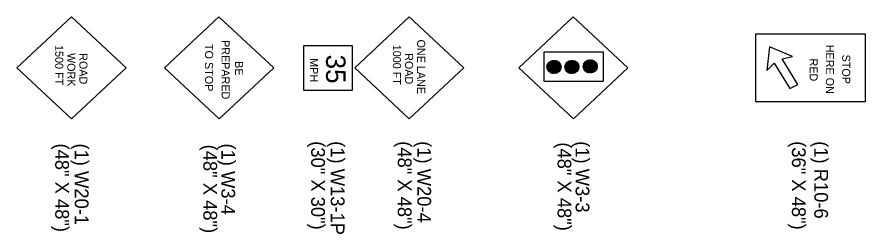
# Model space of a CAD drawing. Extents: x 1807779 to 1818251, y 673292 to 678849.
# Drawn here: x 1811173.9 to 1811561, y 676956.4 to 677055.5 of the extents above; entities that cross this region are included whole.
import ezdxf

# ---------------------------------------------------------------- set-up
doc = ezdxf.new("R2010")
doc.units = 0
doc.layers.add('Default', color=7, linetype='Continuous')

msp = doc.modelspace()

# ---------------------------------------------------------------- linework, layer by layer
at = {"layer": 'Default'}
for p, q in [((1811173.86, 677032.28), (1811198.79, 677055.53)), ((1811223.74, 677032.28), (1811198.79, 677055.53)), ((1811241.19, 677032.24), (1811266.09, 677055.53)), ((1811291.07, 677032.32), (1811266.09, 677055.53)), ((1811328.06, 677032.28), (1811352.98, 677055.53)), ((1811377.93, 677032.28), (1811352.98, 677055.53)), ((1811402.91, 677032.24), (1811427.81, 677055.53)), ((1811452.78, 677032.32), (1811427.81, 677055.53)), ((1811417.45, 677035.31), (1811421.84, 677031.21)), ((1811417.58, 677035.37), (1811421.91, 677031.33)), ((1811417.71, 677035.43), (1811421.97, 677031.46)), ((1811417.85, 677035.49), (1811422.03, 677031.59)), ((1811417.99, 677035.54), (1811422.09, 677031.72)), ((1811418.14, 677035.58), (1811422.13, 677031.86)), ((1811418.3, 677035.62), (1811422.18, 677032.01)), ((1811418.46, 677035.65), (1811422.21, 677032.16)), ((1811418.63, 677035.68), (1811422.24, 677032.32)), ((1811418.81, 677035.69), (1811422.26, 677032.49)), ((1811419, 677035.7), (1811422.26, 677032.66)), ((1811419.2, 677035.7), (1811422.26, 677032.85)), ((1811419.42, 677035.68), (1811422.24, 677033.05)), ((1811419.66, 677035.65), (1811422.21, 677033.27)), ((1811419.91, 677035.59), (1811422.14, 677033.51)), ((1811420.21, 677035.5), (1811422.04, 677033.79)), ((1811420.58, 677035.34), (1811421.87, 677034.13)), ((1811425.52, 677035.27), (1811429.94, 677031.15)), ((1811425.65, 677035.34), (1811430.01, 677031.27)), ((1811425.78, 677035.4), (1811430.08, 677031.39)), ((1811425.91, 677035.46), (1811430.14, 677031.51)), ((1811426.05, 677035.51), (1811430.2, 677031.65)), ((1811426.2, 677035.56), (1811430.25, 677031.78)), ((1811426.35, 677035.6), (1811430.3, 677031.92)), ((1811426.51, 677035.63), (1811430.33, 677032.07)), ((1811426.68, 677035.66), (1811430.37, 677032.23)), ((1811426.85, 677035.69), (1811430.39, 677032.39)), ((1811427.04, 677035.7), (1811430.4, 677032.56)), ((1811427.23, 677035.7), (1811430.41, 677032.74)), ((1811427.44, 677035.69), (1811430.4, 677032.94)), ((1811427.66, 677035.67), (1811430.37, 677033.15)), ((1811427.91, 677035.62), (1811430.32, 677033.37)), ((1811428.18, 677035.55), (1811430.25, 677033.63)), ((1811428.5, 677035.44), (1811430.12, 677033.93)), ((1811433.55, 677035.31), (1811438.08, 677031.1)), ((1811433.67, 677035.4), (1811438.17, 677031.2)), ((1811433.78, 677035.47), (1811438.25, 677031.31)), ((1811433.9, 677035.54), (1811438.32, 677031.42)), ((1811434.03, 677035.61), (1811438.4, 677031.54)), ((1811434.16, 677035.67), (1811438.46, 677031.66)), ((1811434.29, 677035.73), (1811438.53, 677031.79)), ((1811434.44, 677035.78), (1811438.58, 677031.92)), ((1811434.58, 677035.83), (1811438.63, 677032.06)), ((1811434.74, 677035.87), (1811438.68, 677032.2)), ((1811434.89, 677035.91), (1811438.72, 677032.35)), ((1811435.06, 677035.94), (1811438.75, 677032.5)), ((1811435.24, 677035.96), (1811438.77, 677032.67)), ((1811435.42, 677035.97), (1811438.79, 677032.84)), ((1811435.62, 677035.98), (1811438.79, 677033.02)), ((1811435.82, 677035.97), (1811438.78, 677033.21)), ((1811436.05, 677035.94), (1811438.75, 677033.42)), ((1811436.29, 677035.9), (1811438.71, 677033.65)), ((1811436.57, 677035.83), (1811438.63, 677033.9)), ((1811436.89, 677035.71), (1811438.51, 677034.2)), ((1811437.32, 677035.49), (1811438.27, 677034.61)), ((1811198.79, 677009.03), (1811173.86, 677032.28)), ((1811198.79, 677009.03), (1811223.74, 677032.28)), ((1811266.18, 677009.03), (1811241.19, 677032.24)), ((1811266.18, 677009.03), (1811291.07, 677032.32)), ((1811352.98, 677009.03), (1811328.06, 677032.28)), ((1811352.98, 677009.03), (1811377.93, 677032.28)), ((1811427.9, 677009.03), (1811402.91, 677032.24)), ((1811415.83, 677032.93), (1811419.29, 677029.71)), ((1811415.83, 677032.76), (1811419.11, 677029.7)), ((1811415.83, 677032.57), (1811418.91, 677029.7)), ((1811415.84, 677032.37), (1811418.69, 677029.72)), ((1811415.85, 677033.1), (1811419.47, 677029.73)), ((1811415.88, 677033.26), (1811419.64, 677029.75)), ((1811415.88, 677032.16), (1811418.46, 677029.75)), ((1811415.92, 677033.41), (1811419.81, 677029.79)), ((1811415.94, 677031.92), (1811418.2, 677029.81)), ((1811415.96, 677033.56), (1811419.96, 677029.83)), ((1811416.01, 677033.7), (1811420.11, 677029.87)), ((1811416.03, 677031.64), (1811417.91, 677029.89)), ((1811416.12, 677033.96), (1811420.39, 677029.98)), ((1811416.19, 677034.08), (1811420.53, 677030.04)), ((1811416.26, 677034.2), (1811420.65, 677030.1)), ((1811416.33, 677034.32), (1811420.78, 677030.17)), ((1811416.41, 677034.43), (1811420.9, 677030.25)), ((1811416.49, 677034.53), (1811421.01, 677030.33)), ((1811416.58, 677034.64), (1811421.12, 677030.41)), ((1811416.68, 677034.73), (1811421.23, 677030.49)), ((1811416.77, 677034.83), (1811421.33, 677030.58)), ((1811416.87, 677034.92), (1811421.42, 677030.68)), ((1811416.98, 677035), (1811421.51, 677030.78)), ((1811417.09, 677035.09), (1811421.6, 677030.88)), ((1811417.2, 677035.16), (1811421.69, 677030.99)), ((1811417.32, 677035.24), (1811421.77, 677031.1)), ((1811423.97, 677032.84), (1811427.33, 677029.7)), ((1811423.97, 677032.66), (1811427.14, 677029.7)), ((1811423.98, 677033.01), (1811427.52, 677029.72)), ((1811423.98, 677032.46), (1811426.93, 677029.71)), ((1811424, 677032.25), (1811426.71, 677029.73)), ((1811424.01, 677033.17), (1811427.69, 677029.74)), ((1811424.04, 677033.33), (1811427.86, 677029.77)), ((1811424.05, 677032.03), (1811426.46, 677029.78)), ((1811424.08, 677033.48), (1811428.02, 677029.8)), ((1811424.12, 677033.62), (1811428.17, 677029.85)), ((1811424.13, 677031.77), (1811426.19, 677029.85)), ((1811424.17, 677033.76), (1811428.32, 677029.89)), ((1811424.23, 677033.89), (1811428.46, 677029.95)), ((1811424.25, 677031.47), (1811425.86, 677029.97)), ((1811424.29, 677034.01), (1811428.6, 677030)), ((1811424.36, 677034.14), (1811428.73, 677030.07)), ((1811424.43, 677034.25), (1811428.85, 677030.13)), ((1811424.51, 677034.37), (1811428.97, 677030.21)), ((1811424.59, 677034.47), (1811429.09, 677030.28)), ((1811424.68, 677034.58), (1811429.2, 677030.36)), ((1811424.77, 677034.68), (1811429.31, 677030.45)), ((1811424.86, 677034.78), (1811429.41, 677030.53)), ((1811424.96, 677034.87), (1811429.51, 677030.63)), ((1811425.06, 677034.96), (1811429.61, 677030.72)), ((1811425.17, 677035.04), (1811429.7, 677030.82)), ((1811425.28, 677035.12), (1811429.78, 677030.93)), ((1811425.4, 677035.2), (1811429.86, 677031.04)), ((1811427.9, 677009.03), (1811452.78, 677032.32)), ((1811428.94, 677035.22), (1811429.89, 677034.33)), ((1811432.35, 677033.11), (1811435.72, 677029.98)), ((1811432.35, 677032.93), (1811435.52, 677029.98)), ((1811432.36, 677032.74), (1811435.31, 677029.99)), ((1811432.37, 677033.28), (1811435.9, 677029.99)), ((1811432.39, 677033.45), (1811436.08, 677030.01)), ((1811432.39, 677032.53), (1811435.09, 677030.01)), ((1811432.42, 677033.6), (1811436.24, 677030.04)), ((1811432.43, 677032.3), (1811434.84, 677030.05)), ((1811432.46, 677033.75), (1811436.4, 677030.08)), ((1811432.5, 677033.89), (1811436.55, 677030.12)), ((1811432.51, 677032.05), (1811434.57, 677030.12)), ((1811432.56, 677034.03), (1811436.7, 677030.17)), ((1811432.61, 677034.16), (1811436.84, 677030.22)), ((1811432.63, 677031.74), (1811434.25, 677030.24)), ((1811432.67, 677034.29), (1811436.98, 677030.28)), ((1811432.74, 677034.41), (1811437.11, 677030.34)), ((1811432.81, 677034.53), (1811437.23, 677030.41)), ((1811432.89, 677034.64), (1811437.36, 677030.48)), ((1811432.97, 677034.75), (1811437.47, 677030.56)), ((1811433.06, 677034.85), (1811437.58, 677030.64)), ((1811433.15, 677034.95), (1811437.69, 677030.72)), ((1811433.24, 677035.05), (1811437.8, 677030.81)), ((1811433.34, 677035.14), (1811437.89, 677030.9)), ((1811433.45, 677035.23), (1811437.99, 677031)), ((1811416.19, 677031.31), (1811417.55, 677030.04)), ((1811416.62, 677030.73), (1811416.92, 677030.44)), ((1811424.49, 677031.06), (1811425.43, 677030.19)), ((1811432.87, 677031.34), (1811433.81, 677030.46))]:
    msp.add_line(p, q, dxfattribs=at)
for points in [[(1811561.02, 677016.82), (1811511.12, 677016.82), (1811511.12, 677047.82), (1811561.02, 677047.82)], [(1811326.94, 677042.55), (1811326.94, 677022.01), (1811304.89, 677022.01), (1811304.89, 677042.55)], [(1811441.43, 677039.68), (1811441.43, 677026.13), (1811414.57, 677026.13), (1811414.57, 677039.68)], [(1811530.3, 677024.74), (1811523.18, 677036.36), (1811527.84, 677037.52), (1811517.48, 677041.82), (1811516.22, 677031.03), (1811519.6, 677034.39), (1811526.76, 677022.82)]]:
    msp.add_lwpolyline(points, close=True, dxfattribs=at)
for centre in [(1811419.04, 677032.7), (1811427.19, 677032.7), (1811435.57, 677032.98)]:
    msp.add_ellipse(centre, major_axis=(-3.22, 0), ratio=0.93178, dxfattribs=at)

# ---------------------------------------------------------------- texts
for s, height, rotation, p in [('TO STOP', 3.699, 270.0006, (1811259.7, 677043.22)), ('PREPARED', 3.675, 270.1077, (1811267.27, 677044.96)), ('ONE LANE', 3.675, 270.0005, (1811356.54, 677045.21)), ('1500 FT', 3.676, 270.0006, (1811191.32, 677042.7)), ('1000 FT', 3.676, 270.0006, (1811345.51, 677042.84)), ('HERE ON', 3.675, 270.0005, (1811543.16, 677042.82)), ('WORK', 3.674, 270, (1811196.83, 677039.06)), ('ROAD', 3.675, 270.0005, (1811202.35, 677038.99)), ('MPH', 3.676, 270.0006, (1811307.61, 677036.7)), ('35', 8.882, 270, (1811314.97, 677038.34)), ('ROAD', 3.674, 270, (1811351.02, 677039)), ('RED', 3.675, 270.0005, (1811535.73, 677036.54)), ('STOP', 3.675, 270.0005, (1811550.59, 677038.34)), ('BE', 3.675, 270.1078, (1811273.41, 677035.35)), ('(48" X 48")', 6.2623, 270, (1811191.35, 676997.76)), ('(1) W20-1', 6.262, 270, (1811200.28, 676997.76)), ('(48" X 48")', 6.2623, 270, (1811258.95, 676997.24)), ('(1) W3-4', 6.262, 270, (1811267.19, 676997.76)), ('(30" X 30")', 6.2623, 270, (1811308.19, 676998.81)), ('(1) W13-1P', 6.262, 270, (1811317.13, 676998.81)), ('(48" X 48")', 6.2623, 270, (1811347.72, 676998.81)), ('(1) W20-4', 6.262, 270, (1811356.65, 676998.81)), ('(48" X 48")', 6.2623, 270, (1811420.67, 676998.29)), ('(1) W3-3', 6.262, 270, (1811428.91, 676998.81)), ('(36" X 48")', 6.2623, 270, (1811527.65, 676998.81)), ('(1) R10-6', 6.262, 270, (1811537.86, 676998.81))]:
    msp.add_text(s, height=height, rotation=rotation, dxfattribs=at).set_placement(p)

doc.saveas('drawing.dxf')
